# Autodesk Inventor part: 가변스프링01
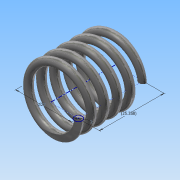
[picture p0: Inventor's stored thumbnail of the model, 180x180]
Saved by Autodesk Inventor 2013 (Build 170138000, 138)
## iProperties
Created: 2014-07
Part Number: 가변스프링01
Material: 강철, 탄소
Document SubType Name: Modeling
Designer: SEMTLE01_MAIN
Density: 7.87 g/cm^3
Mass: 18.7435 g
Surface Area: 32.3996 cm^2
Volume: 2.38164 cm^3
Author: SEMTLE01_MAIN
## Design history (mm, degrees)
sketch "스케치1"
  geometry: L1 (0, 0)-(11, 0); L2 (11, 0)-(11, 25.358); L3 (11, 25.358)-(0, 25.358); L4 (0, 25.358)-(0, 0); C1 r 1.5 at (11, 0)
  constraints: 8 end point, 2 parallel, 1 centre point, 1 coincident, 1 horizontal, 1 perpendicular
  dimensions: "d0" = 3 diameter of C1; "d2" = 22 diameter of L1.end L4; "d3" = 25.35829 distance of L1.end L2.end (derived)
feature "코일1" pitch "d4" = 10; turns "d6" = 5; dims "d5" = 25.35829 (= d3), "d7" = 0, angle "d8" = 90 deg, angle "d9" = 90 deg, "d10" = 0, "d11" = 0
sketch "스케치2"
  geometry: L1 (-12.5, 0)-(-9.5, 0) reference; 1 further point
  constraints: 1 horizontal alignment
extrude "돌출1" cut sketch "스케치2" stored distance "d12" = 10; taper "d13" = 0 deg
node "작업 평면1"
sketch "스케치3"
  geometry: L1 (1.5, 0)-(-1.5, 0) reference; 1 further point
  constraints: 1 horizontal alignment
extrude "돌출2" cut sketch "스케치3" stored distance "d15" = 10; taper "d16" = 0 deg
node "솔리드1"
node "절단 모서리 투영1"
node "절단 모서리 투영2"
other parameters: "d14" = 0
